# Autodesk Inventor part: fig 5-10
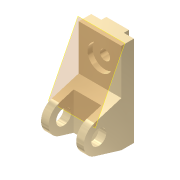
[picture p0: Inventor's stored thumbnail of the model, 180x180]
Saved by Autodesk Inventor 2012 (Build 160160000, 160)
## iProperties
Shininess: 65.0
Angle Display Precision: 2
Document Length Units: 11269
Document Angle Units: 11279
Document Time Units: 11290
Document Mass Units: 11283
Document Length Units Precision: 3
Document Angle Units Precision: 2
Compacted: False
Created: 2001-11
Part Number: fig 5-10
Document SubType Name: Modeling
Designer: Renu Muthoo
Density: 1 g/cm^3
Material: Default
Density: 0.0
Volumn: 0.0
Area: 0.0
PropertySet Name: Model Information
Control State: 0
Master: False
Checked Out: False
Author: Renu Muthoo
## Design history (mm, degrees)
node "Sketch1"
sketch "Sketch2"
  geometry: L1 (33.257, 104.664)-(33.257, -75.336); L2 (33.257, -75.336)-(8.257, -75.336); L3 (8.257, -75.336)-(-45.451, -59.045); L4 (-45.451, -1.628)-(8.257, 14.664); L5 (8.257, 14.664)-(8.257, 104.664); L6 (8.257, 104.664)-(33.257, 104.664); C1 r 15 at (-36.743, -30.336); A1 r 30 centre (-36.743, -30.336) between (-45.451, -1.628) and (-45.451, -59.045)
  constraints: 12 end point, 2 centre point, 2 equal length, 2 parallel, 2 point on circle, 2 tangent, 1 coincident, 1 perpendicular, 1 vertical
  dimensions: "d0" = 180 distance of L1.start L1.end; "d1" = 30 radius of A1; "d2" = 25 distance of L5.end L1.start; "d3" = 45 distance from line of L2 A1.centre; "d4" = 70 distance from line of L1 A1.centre; "d5" = 30 diameter of C1
extrude "Extrusion1" new body sketch "Sketch2" distance "d6" = 85; taper "d7" = 0 deg
workplane "Work Plane1"
sketch "Sketch3"
  geometry: L1 (15, 62.364)-(70, 62.364); L2 (70, 62.364)-(70, -52.386); L3 (70, -52.386)-(15, -52.386); L4 (15, -52.386)-(15, 62.364); L5 (0, -45)-(0, -28.708) reference
  constraints: 8 end point, 2 parallel, 1 horizontal, 1 perpendicular
  dimensions: "d8" = 55 distance of L1.start L1.end; "d9" = 15 distance between parallel lines of L5 L4
extrude "Extrusion2" cut sketch "Sketch3" distance "d10" = 50; taper "d11" = 0 deg
sketch "Sketch4"
  geometry: L1 (0, 25)-(85, 25) reference; L2 (0, 0)-(0, 25) reference; L3 (20, 25)-(65, 25); L4 (65, 25)-(65, 35); L5 (65, 35)-(20, 35); L6 (20, 35)-(20, 25)
  constraints: 8 end point, 2 parallel, 1 horizontal, 1 perpendicular, 1 point on line
  dimensions: "d12" = 45 distance of L4.end L5.end; "d13" = 10 distance of L3.end L4.end; "d14" = 20 distance between parallel lines of L2 L6
extrude "Extrusion3" join sketch "Sketch4" stored distance "d15" = 50; taper "d16" = 0 deg
sketch "Sketch5"
  geometry: L1 (85, 0)-(85, 90) reference; L2 (0, 90)-(85, 90) reference; 1 further point
  dimensions: "d17" = 42 distance from line of L2 point (42.5, 48); "d18" = 42.5 distance from line of L1 point (42.5, 48)
hole "Hole1" sketch "Sketch5" at (42.5, 48) diameter "d19" = 20; stored, may be unused: countersink angle "d23" = 82 deg, drill point angle "d25" = 118 deg; dims "d20" = 6, "d21" = 50, "d22" = 10, "d24" = 8
workplane "Work Plane4"
body "Solid1"
